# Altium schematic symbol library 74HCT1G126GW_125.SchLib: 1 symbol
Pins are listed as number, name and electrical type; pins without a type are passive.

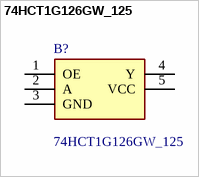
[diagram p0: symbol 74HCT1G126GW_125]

## 74HCT1G126GW_125
designator B?
74HC(T)1G126 - Bus buffer/line driver; 3-state@en-us; Manufacturer_Name: Nexperia; Manufacturer_Part_Number: 74HCT1G126GW,125; Geometry.Height: 1.1mm
footprint SOT65P212X110-5N
pins: 1 OE, 2 A, 3 GND, 4 Y, 5 VCC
